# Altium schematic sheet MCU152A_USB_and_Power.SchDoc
size 431 x 279 mm; Date: Not shown in title block; ApprovedBy: Not shown in title block; CheckedBy: Not shown in title block; Author: Not shown in title block; CompanyName: Not shown in title block; Engineer: Not shown in title block; Organization: Not shown in title block; Address1: Not shown in title block; Address2: Not shown in title block; Address3: Not shown in title block; Address4: Not shown in title block; DocumentNumber: 6; Revision: Use project parameter SCH_Rev; SheetNumber: 6; SheetTotal: 8; PageSetup: Record=PageOptions¦CenterHorizontal=True¦CenterVertical=True¦PrintScale=1.00¦XCorrection=1.00¦YCorrection=1.00¦PrintKind=0¦BorderSize=5000000¦LeftOffset=0¦BottomOffset=0¦Orientation=2¦PaperLength=1000¦PaperWidth=1000¦Scale=100¦PaperSource=15¦PrintQuality=600¦MediaType=1¦DitherType=10¦PaperKind=Letter¦PrintScaleMode=1
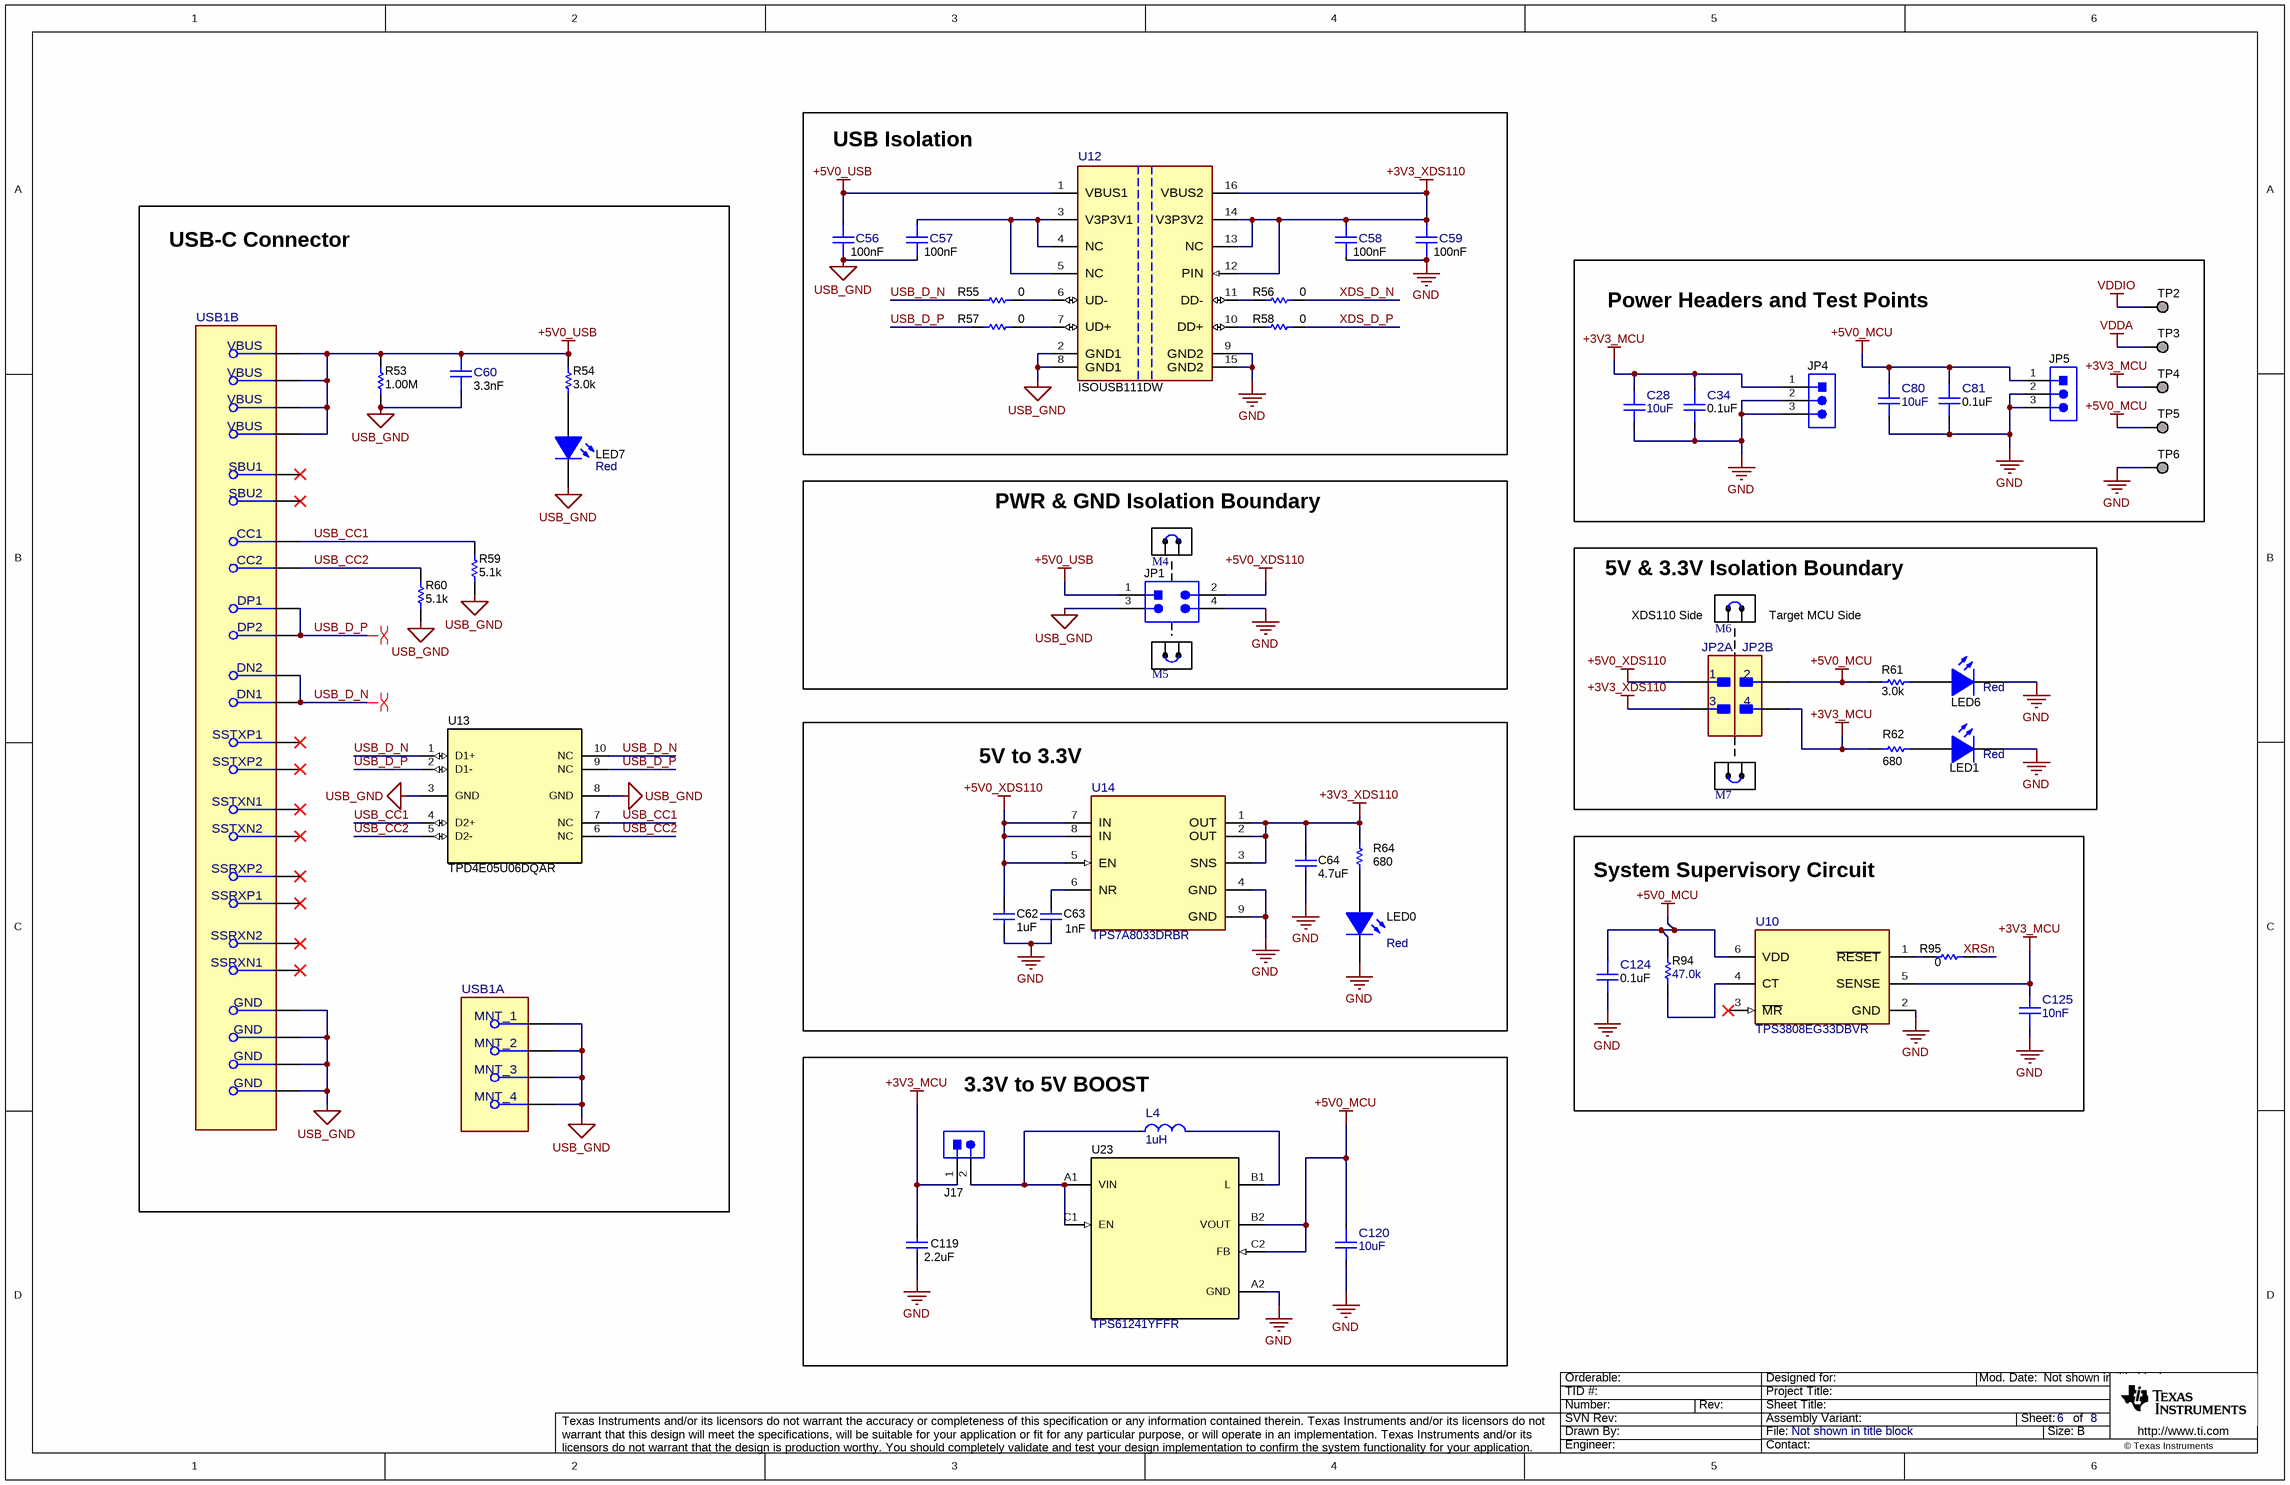
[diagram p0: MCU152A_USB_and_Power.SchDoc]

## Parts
C28  ValueDisplayed: 10uF  [FP-885012106031_0603-MFG]  (hidden comment: 885012106031)
C34  ValueDisplayed: 0.1uF  [FP-885012205018_0402-MFG]  (hidden comment: 885012205018)
C56  Cap_F: 100nF  [FP-885012205018_0402-MFG]  (hidden comment: 885012205018)
C57  Cap_F: 100nF  [FP-885012205018_0402-MFG]  (hidden comment: 885012205018)
C58  Cap_F: 100nF  [FP-885012205018_0402-MFG]  (hidden comment: 885012205018)
C59  Cap_F: 100nF  [FP-885012205018_0402-MFG]  (hidden comment: 885012205018)
C60  ValueDisplayed: 3.3nF  [FP-885012205064_0402-MFG]  (hidden comment: 885012205064)
C62  ValueDisplayed: 1uF  [0402]  (hidden comment: 885012105012)
C63  Cap_F: 1nF  [0402]  (hidden comment: 885012205061)
C64  ValueDisplayed: 4.7uF  [0402_065]  (hidden comment: C1005X5R1A475K050BC)
C80  ValueDisplayed: 10uF  [FP-885012106031_0603-MFG]  (hidden comment: 885012106031)
C81  ValueDisplayed: 0.1uF  [FP-885012205018_0402-MFG]  (hidden comment: 885012205018)
C119  ValueDisplayed: 2.2uF  [0603]  (hidden comment: 885012106018)
C120  ValueDisplayed: 10uF  [FP-885012106031_0603-MFG]  (hidden comment: 885012106031)
C124  ValueDisplayed: 0.1uF  [FP-885012205018_0402-MFG]  (hidden comment: 885012205018)
C125  Cap_F: 10nF  [FP-885012206040_0603-MFG]  (hidden comment: 885012206040)
J17  61300211121  [WURTH_61300211121]  (value not drawn)
JP1  TSM-102-01-L-DV  [Samtec_TSM-102-01-x-DV]  (value not drawn)
JP2  61300421121  [FP-61300421121_HDR4-MFG]  (value not drawn)  (parts A,B of 2)
JP4  61300311121  [WURTH_61300311121]  (value not drawn)
JP5  61300311121  [WURTH_61300311121]  (value not drawn)
L4  value 1uH  [FP-74479773210_0805-MFG]  (hidden comment: 74479773210)
LED0  value Red  [WL-SMCW_RED_0805]  (hidden comment: 150080SS75000)
LED1  value Red  [WL-SMCW_RED_0805]  (hidden comment: 150080SS75000)
LED6  value Red  [WL-SMCW_RED_0805]  (hidden comment: 150080SS75000)
LED7  value Red  [WL-SMCW_RED_0805]  (hidden comment: 150080SS75000)
M4  60900213421  [Wurth_60900213421]  (value not drawn)
M5  60900213421  [Wurth_60900213421]  (value not drawn)
M6  60900213421  [Wurth_60900213421]  (value not drawn)
M7  60900213421  [Wurth_60900213421]  (value not drawn)
R53  ValueDisplayed: 1.00M  [0402]  (hidden comment: CRCW04021M00FKED)
R54  ValueDisplayed: 3.0k  [0603]  (hidden comment: RC0603JR-073KL)
R55  ValueDisplayed: 0  [0402]  (hidden comment: RC0402JR-070RL)
R56  ValueDisplayed: 0  [0402]  (hidden comment: RC0402JR-070RL)
R57  ValueDisplayed: 0  [0402]  (hidden comment: RC0402JR-070RL)
R58  ValueDisplayed: 0  [0402]  (hidden comment: RC0402JR-070RL)
R59  ValueDisplayed: 5.1k  [0603]  (hidden comment: RC0603JR-075K1L)
R60  ValueDisplayed: 5.1k  [0603]  (hidden comment: RC0603JR-075K1L)
R61  ValueDisplayed: 3.0k  [0603]  (hidden comment: RC0603JR-073KL)
R62  ValueDisplayed: 680  [0402]  (hidden comment: CRCW0402680RJNED)
R64  ValueDisplayed: 680  [0402]  (hidden comment: CRCW0402680RJNED)
R94  ValueDisplayed: 47.0k  [0603]  (hidden comment: RC0603FR-0747KL)
R95  ValueDisplayed: 0  [0603]  (hidden comment: ERJ-3GEY0R00V)
TP2  TESTPOINT  [TP_50MIL-25MILHOLE]  (value not drawn)  (no BOM)
TP3  TESTPOINT  [TP_50MIL-25MILHOLE]  (value not drawn)  (no BOM)
TP4  TESTPOINT  [TP_50MIL-25MILHOLE]  (value not drawn)  (no BOM)
TP5  TESTPOINT  [TP_50MIL-25MILHOLE]  (value not drawn)  (no BOM)
TP6  TESTPOINT  [TP_50MIL-25MILHOLE]  (value not drawn)  (no BOM)
U10  TPS3808EG33DBVR  [DBV0006A-MFG]
U12  ISOUSB111DW  [DW0016B-MFG]
U13  TPD4E05U06DQAR  [DQA0010A]
U14  TPS7A8033DRBR  [DRB0008A-MFG]
U23  TPS61241YFFR  [YFF0006AEAE]
USB1  MUP-U22001  [FP-MUP-U22001_CONN_USB_8MM94_8MM0-MFG]  (value not drawn)  (parts A,B of 2)

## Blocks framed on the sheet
USB Isolation: C56-C59 R55-R58 U12
USB-C Connector: C60 LED7 R53 R54 R59 R60 U13 USB1
Power Headers and Test Points: C28 C34 C80 C81 JP4 JP5 TP2-TP6
PWR & GND Isolation Boundary: JP1 M4 M5
5V & 3.3V Isolation Boundary: JP2 LED1 LED6 M6 M7 R61 R62
5V to 3.3V: C62-C64 LED0 R64 U14
System Supervisory Circuit: C124 C125 R94 R95 U10
3.3V to 5V BOOST: C119 C120 J17 L4 U23

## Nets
+3V3_MCU: C28.1 C34.1 C119.1 C125.2 J17.1 JP2.4 JP4.1 R62.2 TP4.1 U10.5(SENSE)
+3V3_XDS110: C58.2 C59.2 C64.1 JP2.3 R64.2 U12.12(PIN) U12.13(NC) U12.14(V3P3V2) U12.16(VBUS2) U14.1(OUT) U14.2(OUT) U14.3(SNS)
+5V0_MCU: C80.1 C81.1 C120.1 C124.1 JP2.2 JP5.1 R61.2 R94.2 TP5.1 U10.6(VDD) U23.B2(VOUT) U23.C2(FB)
+5V0_USB: C56.2 C60.2 JP1.1 R53.2 R54.2 U12.1(VBUS1) USB1.A4(VBUS) USB1.A9(VBUS) USB1.B4(VBUS) USB1.B9(VBUS)
+5V0_XDS110: C62.1 JP1.2 JP2.1 U14.5(EN) U14.7(IN) U14.8(IN)
GND: C28.2 C34.2 C58.1 C59.1 C62.2 C63.2 C64.2 C80.2 C81.2 C119.2 C120.2 C124.2 C125.1 JP1.4 JP4.2 JP4.3 JP5.2 JP5.3 LED0.1(K) LED1.1(K) LED6.1(K) TP6.1 U10.2(GND) U12.9(GND2) U12.15(GND2) U14.4(GND) U14.9(GND) U23.A2(GND)
USB_GND: C56.1 C57.1 C60.1 JP1.3 LED7.1(K) R53.1 R59.1 R60.1 U12.2(GND1) U12.8(GND1) U13.3(GND) U13.8(GND) USB1.1(MNT_1) USB1.2(MNT_2) USB1.3(MNT_3) USB1.4(MNT_4) USB1.A1(GND) USB1.A12(GND) USB1.B1(GND) USB1.B12(GND)
VDDA: TP3.1
VDDIO: TP2.1
USB_CC1: R59.2 U13.4(D2+) U13.7(NC) USB1.A5(CC1)
USB_CC2: R60.2 U13.5(D2-) U13.6(NC) USB1.B5(CC2)
USB_D_N: R55.1 U13.1(D1+) U13.10(NC) USB1.A7(DN1) USB1.B7(DN2)
USB_D_P: R57.1 U13.2(D1-) U13.9(NC) USB1.A6(DP1) USB1.B6(DP2)
XDS_D_N: R56.2
XDS_D_P: R58.2
XRSn: R95.1
NetC57_2: C57.2 U12.3(V3P3V1) U12.4(NC) U12.5(NC)
NetC63_1: C63.1 U14.6(NR)
NetJ17_2: J17.2 L4.1 U23.A1(VIN) U23.C1(EN)
NetL4_2: L4.2 U23.B1(L)
NetLED0_2: LED0.2(A) R64.1
NetLED1_2: LED1.2(A) R62.1
NetLED6_2: LED6.2(A) R61.1
NetLED7_2: LED7.2(A) R54.1
NetR55_2: R55.2 U12.6(UD-)
NetR56_1: R56.1 U12.11(DD-)
NetR57_2: R57.2 U12.7(UD+)
NetR58_1: R58.1 U12.10(DD+)
NetR94_1: R94.1 U10.4(CT)
NetR95_2: R95.2 U10.1(~{RESET})

Not connected (* = marked no-connect by the designer): U10 3(~{MR})*; USB1 A2(SSTXP1)* A3(SSTXN1)* A8(SBU1)* A10(SSRXN2)* A11(SSRXP2)* B2(SSTXP2)* B3(SSTXN2)* B8(SBU2)* B10(SSRXN1)* B11(SSRXP1)*

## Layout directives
differential pair: USB_D_N, USB_D_P

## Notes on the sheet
- XDS110 Side
- (near M6) Target MCU Side

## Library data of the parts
C28 C80 C120 = CMP-0124926-1: 10 µF ±20% 25V Ceramic Capacitor X5R 0603 (1608 Metric); Manufacturer: Wurth; AEC Qualified: No; Cap_F: 10µF; SizeZ_mm: 1mm; TempCo: 15%; Value: 10µF
C34 C81 C124 = CMP-0090362-1: 0.1µF ±10% 10V Ceramic Capacitor X7R 0402 (1005 Metric); Manufacturer: Wurth Electronics; AEC Qualified: No; Value: 100nF; SizeZ_mm: 0.55mm; TempCo: 15%
C56-C59 = CMP-0090362-1: 0.1µF ±10% 10V Ceramic Capacitor X7R 0402 (1005 Metric); Manufacturer: Wurth Electronics; AEC Qualified: No; Value: 100nF; SizeZ_mm: 0.55mm; ValueDisplayed: 100000pF; TempCo: 15%
C60 = CMP-0092424-1: Cap Cer 3300pF 50V X7R 0402; Manufacturer: Wurth Electronics; TempCo: 15%; AEC Qualified: No; Value: 3.3nF; SizeZ_mm: 0.55mm; Tolerance_%: 10%
C62 = CMP-0064924-2: CAP, CERM, 1 uF, 10 V,+/- 20%, X5R, 0402; Manufacturer: Wurth Elektronik; Polarized: N; Value: 1uF; U/M: EA; Cap_F: 1µF; Value1: Unknown; VDC_V: 10V; TaMin_C: -55°C; TaMax_C: 85°C; SizeArea_mm2: 0.5; SizeAreaWB_mm2: 3; SizeX_mm: 1; SizeZ_mm: 0.6; AEC Category: Q200
C63 = CMP-0006231-2: CAP, CERM, 1000 pF, 50 V, +/- 10%, X7R, 0402; Manufacturer: Wurth Elektronik; Polarized: N; Value: 1000pF; U/M: EA; Value1: Unknown; VDC_V: 50V; TaMin_C: -55°C; TaMax_C: 125°C; SizeArea_mm2: 0.5; SizeAreaWB_mm2: 3; SizeX_mm: 1; SizeZ_mm: 0.6; AEC Category: Q200
C64 = CMP-0006268-2: CAP, CERM, 4.7 uF, 10 V, +/- 10%, X5R, 0402; Manufacturer: TDK; TaMin_C: -55°C; ESR_ohm: 3.417m; Polarized: N; SizeAreaWB_mm2: 3; Value1: 0.003417 ohm; U/M: EA; Value: 4.7uF; TaMax_C: 85°C; SizeZ_mm: 0.65; SizeX_mm: 1; SizeY_mm: 0.5; Value2: 10V; Cap_F: 4.7µF; IRMS_A: 2.7063A; AEC Category: Q200
C119 = CMP-0006825-5: CAP, CERM, 2.2 uF, 16 V, +/- 20%, X5R, 0603; Manufacturer: Wurth Elektronik; TaMin_C: -55°C; Polarized: N; SizeAreaWB_mm2: 4.68; Value1: Unknown; U/M: EA; Value: 2.2uF; TaMax_C: 85°C; SizeZ_mm: 1; SizeX_mm: 1.6; SizeY_mm: 0.8; Value2: 16V; SizeArea_mm2: 1.28; Cap_F: 2.2µF; AEC Category: Q200
C125 = CMP-0124908-1: 10000 pF ±10% 16V Ceramic Capacitor X7R 0603 (1608 Metric); Manufacturer: Wurth; AEC Qualified: No; SizeZ_mm: 0.87mm; TempCo: 15%; Value: 10nF
J17 = CMP-0054794-2: Header, 2.54 mm, 2x1, Gold, TH; Manufacturer: Wurth Elektronik; Shrouded: N; Gender: Male; Green_REACh: Passed; Pitch_mm: 2.54; Green_Lifecycle: Active; Row_Count: 1; Cert_UL: Y
JP1 = CMP-0055559-1: Header, 2.54mm, 2x2, Gold, SMT; Manufacturer: Samtec; CNHeader: TRUE; Shrouded: N; Gender: Male; Cert_CSA: Y; Voltage_V: 475V; Row_Count: 2; Pitch_mm: 2.54; CT: FALSE
JP2 = CMP-0092422-1: THT Vertical Pin Header WR-PHD, Pitch 2.54 mm, Dual Row, 4 pins; Manufacturer: Wurth Electronics; DUT-Pitch_mm: 2.54mm; SizeZ_mm: 8.89mm; Voltage_V: 250V; Conn Gender: Male; AEC Qualified: No; Row_Count: 2; ContactFinish: Gold; Conn Orientation: Straight; Current_A: 3A
JP4 JP5 = CMP-0054796-1: Header, 2.54 mm, 3x1, Gold, TH; Manufacturer: Wurth Elektronik; Green_Lifecycle: Active; Green_REACh: Passed; CNHeader: TRUE; CT: FALSE
L4 = CMP-0124907-1: Inductor Power Shielded Multi-Layer 1uH 20% 1MHz 14Q-Factor Powdered Iron 1.2A 180mOhm DCR 0805 T/R; Manufacturer: Wurth; AEC Qualified: No; DCR_ohm: 0.225; Ind_H: 1µH; Irms: 1200mA; Isat: 800mA; SizeZ_mm: 0.6mm; Q Factor: 14; Self Resonant Frequency: 90MHz; TaMax_C: +85°C; TaMin_C: -40°C
LED0 LED1 LED6 LED7 = CMP-0002951-3: LED, Red, SMD; Manufacturer: Wurth Elektronik; Type: AlInGaP; Vf_V: 1.9V; Io_A: 30mA; Vr_V: 5V; Ir_A: 25µA; Tjmax_C: 85°C; Power_TotalModule: 72mW; Value1: 0.072W; Angle: 140
M4-M7 = CMP-0003761-2: Shunt, 2.54mm, Gold, Black; Manufacturer: Wurth Elektronik
R53 = CMP-0026100-2: RES, 1.00 M, 1%, 0.063 W, AEC-Q200 Grade 0, 0402; Manufacturer: Vishay-Dale; Value: 1.00Meg; Res_ohm: 1M; Value_Code: 1M00; Power_W: 63mW; Value2: 0.063W; VDC_V: 50V; TempCo: 100 ppm/C; SizeArea_mm2: 0.5; SizeX_mm: 1; SizeZ_mm: 0.6; EIA_Code: E96; AEC Category: Q200; AEC Qualified: Y; AEC Grade: 0
R54 R61 = CMP-0025921-5: RES, 3.0 k, 5%, 0.1 W, 0603; Manufacturer: Yageo; Power_W: 100mW; TempCo: 100 ppm/C; Value_Code: 3k00; Value: 3.0k; EIA_Code: E24; Res_ohm: 3k; SizeX_mm: 1.6; SizeY_mm: 0.8; SizeZ_mm: 1; Value2: 0.1W; SizeArea_mm2: 1.28; AEC Qualified: N; VDC_V: 75V; AEC Category: Q200; SizeAreaWB_mm2: 4.68
R55-R58 = CMP-0027004-2: RES, 0, 5%, 0.063 W, 0402; Manufacturer: Yageo America; Power_W: 63mW; TempCo: 200 ppm/C; Value_Code: 0000; U/M: EA; Value: 0; EIA_Code: E24; SizeX_mm: 1; SizeY_mm: 0.5; SizeZ_mm: 0.6; Value2: 0.063W; VDC_V: 50V; AEC Category: Q200
R59 R60 = CMP-0025932-5: RES, 5.1 k, 5%, 0.1 W, 0603; Manufacturer: Yageo; Power_W: 100mW; TempCo: 100 ppm/C; Value_Code: 5k10; Value: 5.1k; EIA_Code: E24; SizeX_mm: 1.6; SizeY_mm: 0.8; SizeZ_mm: 1; Value2: 0.1W; SizeArea_mm2: 1.28; AEC Qualified: N; VDC_V: 75V; AEC Category: Q200; SizeAreaWB_mm2: 4.68
R62 R64 = CMP-0026962-3: RES, 680, 5%, 0.063 W, AEC-Q200 Grade 0, 0402; Manufacturer: Vishay-Dale; Power_W: 63mW; TempCo: 200 ppm/C; Value_Code: 680R; Value: 680; EIA_Code: E24; SizeX_mm: 1; SizeY_mm: 0.5; SizeZ_mm: 0.6; Value2: 0.063W; AEC Qualified: Y; VDC_V: 50V; AEC Category: Q200; AEC Grade: 0
R94 = CMP-0023133-5: RES, 47.0 k, 1%, 0.1 W, 0603; Manufacturer: Yageo; Power_W: 100mW; TempCo: 100 ppm/C; Value_Code: 47k0; Value: 47.0k; Res_ohm: 47k; SizeX_mm: 1.6; SizeY_mm: 0.8; SizeZ_mm: 1; Value2: 0.1W; SizeArea_mm2: 1.28; AEC Qualified: N; VDC_V: 75V; AEC Category: Q200; SizeAreaWB_mm2: 4.68
R95 = CMP-0025874-4: RES, 0, 5%, 0.1 W, AEC-Q200 Grade 0, 0603; Manufacturer: Panasonic; Power_W: 100mW; TempCo: 600 ppm/C; Value_Code: 0000; Value: 0; EIA_Code: E24; SizeX_mm: 1.6; SizeY_mm: 0.8; SizeZ_mm: 1; Value2: 0.1W; SizeArea_mm2: 1.28; AEC Qualified: Y; VDC_V: 50V; AEC Category: Q200; SizeAreaWB_mm2: 4.68
TP2-TP6 = CMP-0078143-3: TEST POINT.  No entry in BOM.
U10 = CMP-0120241-1: Low-quiescent current supervisor with programmable delay and manual reset 6-SOT-23 -40 to 85; Manufacturer: Texas Instruments; SizeZ_mm: 1.45mm; AEC Qualified: No; Max Supply Voltage: 6V; Min Supply Voltage: 1.7V; Nominal Supply Current: 0.6uA; Number Of Outputs: 1; Reset Timeout: 0.02-0.83s; Reset Type: Active Low; Standoff Height: 0mm; Threshold Voltage: 3.07V; TJmax_C: +125°C
U12 = CMP-0091303-1: Full/Low Speed Isolated USB Repeater, SOIC16-Wide; Manufacturer: Texas Instruments; Number Of Ports: 1; Usb Standard: USB 2.0; Min Supply Voltage: 3V; Data Rate: 12Mbits/s; Max Supply Voltage: 5.5V; TaMin_C: -40°C; SizeZ_mm: 2.65mm; TaMax_C: +125°C; Nominal Supply Current: 9-9.5mA; TJmax_C: +150°C; Standoff Height: 0.1mm; AEC Qualified: No
U13 = CMP-0073613-3: 4-Channel Ultra-Low-Capacitance IEC ESD Protection Diode, DQA0010A (USON-10); Alternate Manufacturer: Texas Instruments; Green_Lifecycle: Active; SizeAreaWB_mm2: 7.0; Green_REACh: Passed; SizeZ_mm: 0.55; SizeX_mm: 1.0; SizeY_mm: 2.5; CompType: IC; AEC Category: Q200; AEC Qualified: N
U14 = CMP-0124913-1: Low-Noise, Wide-Bandwidth, High PSRR, Low-Dropout 1-A Linear Regulator; Manufacturer: Texas Instruments; SizeZ_mm: 1mm; AEC Qualified: No; Dropout Voltage: 500mV; Max Supply Voltage: 6.5V; Min Supply Voltage: 3.8V; Nominal Supply Current: 120uA; Number Of Outputs: 1; Output Type: Fixed; Output Voltage: 3.3V; Standoff Height: 0mm; TJmax_C: +125°C
U23 = CMP-0067212-2: 5V, 500mA, 4MHz Step-Up DC/DC Converter, YFF0006AEAE (DSBGA-6); Alternate Manufacturer: Texas Instruments; Alternate PartNumber: TPS61241YFFT; AEC Qualified: N; Rating: Catalog; SizeX_mm: 0.856; SizeAreaWB_mm2: 4.190848; SizeY_mm: 1.258; SizeArea_mm2: 1.076848; AEC Category: Q200; CompType: IC; SizeZ_mm: 0.625
USB1 = CMP-0092137-1: Connector, USB Type-C 24 pin Mid Mount dual row Receptacle Surface Mount; Manufacturer: MUP; ContactFinish: Gold,Nickel; Usb Standard: OTHER; AEC Qualified: No; Conn Orientation: Horizontal; Shrouded: true; SizeZ_mm: 2.81mm; Is Female: yes; DUT-Pitch_mm: 0.5mm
